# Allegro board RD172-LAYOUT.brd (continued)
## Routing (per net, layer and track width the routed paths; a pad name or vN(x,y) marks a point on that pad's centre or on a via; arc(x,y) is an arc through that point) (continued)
N18175855: length 2.4
  TOP w0.8: D21.A 209.08,140.28 208.3,139.5 R77.2
N18175865: length 4.1
  TOP w1: D21.C 209.8,135.6 208.3,134.1 207.35,134.1
  TOP w1.4: D29.A 207.35,134.1
N18186220: length 22.9
  TOP w0.2: v1(195.2,16.5) 195.89,16.3 206.3,16.3 207.4,17.4 R139.1
  TOP w0.35: 194.21,11.6 v1(195.2,11.6) ; IC19.13 194.32,17.38 v1(195.2,16.5)
  TOP w0.8: R137.1 194.21,11.6
  BOTTOM w0.35: v1(195.2,11.6) 196,12.4 196,15.7 v1(195.2,16.5)
N18186262: length 25.3
  TOP w0.2: R140.1 212.1,16.4 211.5,15.8 194.68,15.8 v1(194.28,16.2)
  TOP w0.35: 194.21,13.2 v1(195.2,13.2) ; IC19.12 193.75,16.73 v1(194.28,16.2)
  TOP w0.8: R138.1 194.21,13.2
  BOTTOM w0.35: v1(194.28,16.2) 195.2,15.28 v1(195.2,13.2)
N18188625: length 135.2
  TOP w1: F1.1 15.25,106 ; F1.1 13.25,108 ; F1.1 13.25,104
  TOP w2: 21,89.6 TB1.2 ; TB1.2 17,87.5 ; TB1.2 13,89.6 ; TB1.2 17,92.35 ; TB1.1 21,98.4 ; TB1.1 17,101.15 ; TB1.1 13,98.4 ; TB1.1 17,95.65
  CONDUCTIVE2 w1: F1.1 15.15,106 ; F1.1 13.25,104.1 ; F1.1 13.25,107.9
  CONDUCTIVE2 w2: 17,87.5 TB1.2 ; TB1.2 TB1.1 ; TB1.2 13,89.6 ; TB1.2 21,89.6 ; TB1.1 13,98.4 ; TB1.1 21,98.4 ; TB1.1 17,102.1
  CONDUCTIVE3 w1: F1.1 13.25,104.1 ; F1.1 13.25,107.9 ; F1.1 15.15,106
  CONDUCTIVE3 w2: TB1.2 17,87.5 ; TB1.2 13,89.6 ; TB1.2 17,92.35 ; TB1.2 21,89.6 ; TB1.1 17,101.5 ; TB1.1 21,98.4 ; TB1.1 13,98.4 ; TB1.1 17,95.5
  BOTTOM w1: F1.1 13.25,104 ; F1.1 15.25,106 ; F1.1 13.25,108
  BOTTOM w2: 17,87.5 TB1.2 ; TB1.2 17,92 ; TB1.2 13,89.6 ; TB1.2 21,89.6 ; TB1.1 17,94.5 ; TB1.1 17,102 ; TB1.1 13,98.4 ; TB1.1 21,98.4
N18188823: length 54.9
  CONDUCTIVE3 w1: C8.1 49,87.3 ; C8.1 47.5,89 ; C8.1 50.7,89 ; C8.1 49,90.7
  CONDUCTIVE3 w1.5: L1.3 64,126.75 ; L1.3 61.75,124.5 ; L1.3 64,122.25 ; L1.3 L2.1 ; L2.1 70,126.75 ; L2.1 70,122.25 ; L2.1 72.25,124.5
  BOTTOM w1: C8.1 49,90.8 ; C8.1 50.8,89 ; C8.1 49,87.2 ; C8.1 47.5,89
  BOTTOM w1.5: L1.3 61.35,124.5 ; L1.3 64,121.85 ; L1.3 L2.1 ; L1.3 64,127.15 ; L2.1 70,121.85 ; L2.1 70,127.15 ; L2.1 72.65,124.5
N18188901: length 24.7
  TOP w1: C9.1 56,87.5 ; C9.1 54.5,89 ; C9.1 57.5,89 ; C9.1 56,90.8
  TOP w3.5: L1.1 L2.3
  CONDUCTIVE2 w1: C9.1 56,87.5 ; C9.1 54.5,89 ; C9.1 57.7,89 ; C9.1 56,90.7
  CONDUCTIVE2 w3.5: L2.3 L1.1
N18189364: length 1.9
  TOP w0.3: 69.6,12.51 69.6,10.99
  TOP w0.8: 69.6,10.99 LED1.A ; R11.2 69.6,12.51
N18189573: length 2.4
  TOP w0.5: 129.15,158.23 128.51,158.23 127.74,159 R13.1
  TOP w0.8: PC2.6 129.15,158.23
N18189577: length 7.6
  TOP w0.3: 137.69,158.7 138.81,158.7 ; 137.31,158.7 136.41,158.7 136.23,158.52 135.85,158.23 ; 139.19,158.7 140.63,158.7 140.83,158.5 142.73,158.5
  TOP w0.8: 137.69,158.7 R15.1 137.31,158.7 ; 139.19,158.7 R14.2 138.81,158.7 ; PC2.1 135.85,158.23
  TOP w1.7: 142.73,158.5 TP12.1
N18189655: length 37.5
  TOP w0.3: v1(128.2,160.77) 128.98,160.77 ; 95.7,161.31 v1(95.7,160.2)
  TOP w0.5: Q2.G R17.2
  TOP w0.8: R17.2 95.7,161.31 ; 128.98,160.77 PC2.4
  BOTTOM w0.3: v1(128.2,160.77) 126.93,159.5 115.4,159.5 114.7,160.2 v1(95.7,160.2)
N18196094: length 1.7
  TOP w0.3: 155.19,55.3 156.52,55.3
  TOP w0.8: 156.52,55.3 R43.1 ; R44.1 155.19,55.3
N18196224: length 1.5
  TOP w0.3: 153.69,53.7 154.81,53.7
  TOP w0.8: 154.81,53.7 R44.2 ; R45.2 153.69,53.7
N18196230: length 1.6
  TOP w0.3: 229.69,51.4 230.91,51.4
  TOP w0.8: 230.91,51.4 R24.2 ; R25.2 229.69,51.4
N18197780: length 1.5
  TOP w0.8: R59.2 R58.2
N18197809: length 1.5
  TOP w0.3: 156.3,143.51 156.3,142.39
  TOP w0.8: R58.1 156.3,143.51 ; 156.3,142.39 R57.1
N18259366: length 2
  TOP w0.35: LED4.C R137.2
N18259444: length 2
  TOP w0.35: LED5.C R138.2
N18316829: length 8.5
  TOP w0.25: 97.7,52.22 97.7,52.67 ; 99.2,51.83 99.2,50.7 R79.1
  TOP w0.3: R78.2 98.4,52.8 97.7,52.8 ; 97.7,52.8 95.6,52.8 95.1,52.3 IC13.13 ; 97.7,52.8 97.7,52.67
  TOP w0.45: C70.1 97.7,52.22
  TOP w0.8: R78.2 99.2,51.83
N18316863: length 14
  TOP w0.3: 95.84,58.1 95.84,57.42 ; 95.84,58.1 95.5,58.1 95.1,57.7 IC13.2 ; 95.84,58.1 99.65,58.1 101.6,56.15 101.6,52.8 R78.1
  TOP w0.5: IC13.1 95.84,57.42
N18316907: length 9.1
  TOP w0.3: 91.76,56.38 91.76,55.7 92.1,55.36 92.5,55.36 ; 92.5,55.36 96.36,55.36 96.8,55.8 97.61,55.8 ; 92.5,55.36 IC13.6
  TOP w0.5: IC13.7 91.76,56.38
  TOP w0.8: 97.61,55.8 R80.1
N18316911: length 8.7
  TOP w0.25: R81.1 100.15,54.12 100.75,54.12 ; 94.45,51.62 94.45,52.9 95.75,54.2 97.63,54.2 ; 97.97,54.2 99.23,54.2
  TOP w0.35: 94.45,51.62 IC13.12
  TOP w0.45: C73.1 100.75,54.12
  TOP w0.8: 99.23,54.2 R81.1 ; 97.63,54.2 R80.2 97.97,54.2
N18317049: length 10.9
  TOP w0.3: TP44.1 93,63.6 94.45,65.05 94.45,66.88 ; IC13.5 93.15,57.9 93,58.05 93,61.93
  TOP w1.5: 94.45,66.88 CT1.VO
  TOP w1.7: 93,61.93 TP44.1
N18317051: length 11.1
  TOP w0.3: IC13.3 94.45,58.1 96.4,60.05 96.4,62.15 ; 96.4,62.47 96.4,65.01 96.36,65.05 96.36,66.88
  TOP w1.5: CT1.VREF 96.36,66.88
  TOP w1.7: 96.4,62.47 TP45.1 96.4,62.15
N18317079: length 7.8
  TOP w0.3: 93.71,48.4 92.49,48.4 ; C74.1 92.3,48.9 93.15,49.75 IC13.10 ; D22.C/A 96,47.35 94.95,48.4 94.09,48.4
  TOP w0.8: 93.71,48.4 R83.1 94.09,48.4 ; 92.49,48.4 C74.1
N18317089: length 11
  TOP w0.2: 93.7,44.2 94.4,44.2 ; 93.7,45.3 94.4,45.3
  TOP w0.3: 97.08,42.5 96,42.5 95.5,43 94.4,43 ; 94.1,41.75 94.1,42.7 94.4,43 ; 94.4,43 94.4,45.8 93.9,46.3 93.9,46.78
  TOP w0.45: 93.58,45.3 93.7,45.3 ; 93.58,44.2 93.7,44.2
  TOP w0.8: 97.08,42.5 R82.1 ; R83.2 93.9,46.78
  TOP w1: 94.1,41.75 CN7.1
N18318229: length 8
  TOP w0.25: v1(265.7,29) 264.77,29
  TOP w0.3: IC16.7 267.4,32.28 v1(267.4,29)
  TOP w0.8: 264.77,29 R112.1
  BOTTOM w0.25: v1(265.7,29) v1(267.4,29)
N18318249: length 6.5
  TOP w0.3: IC16.6 266.5,32.4 266.5,28 R107.1
N18318251: length 8
  TOP w0.3: 264.11,27.4 263.3,27.4 263.1,27.6 262.2,27.6 261.8,27.2 IC17.2 ; 264.3,27.21 264.3,25.79 ; R108.1 265,26.3 265.9,26.3 266,26.2 266,25.74
  TOP w0.45: 266,25.74 C94.1
  TOP w0.8: 264.3,27.21 R107.2 264.11,27.4 ; 264.3,25.79 R108.1
N18318261: length 2.3
  TOP w0.3: IC16.5 263.6,32.5 263.6,32 263.8,31.8 L9.2
N18318275: length 6.4
  TOP w0.3: 263,29.19 263,30.4 263.2,30.6 263.83,30.6 ; 261.5,28.42 261.5,27.8 261.15,27.45 IC17.3 ; 261.69,28.61 262.61,28.61 R112.2
  TOP w0.45: C95.2 263.83,30.6
  TOP w0.8: 261.69,28.61 R113.2 261.5,28.42 ; 263,29.19 R112.2
N18318401: length 5.4
  TOP w0.25: 262.2,18.33 262.2,17.17 ; 262.2,18.62 262.2,19.1 261.8,19.5 261.8,20.07 ; 262.2,16.83 262.2,15.57
  TOP w0.35: IC17.13 261.8,20.07
  TOP w0.8: 262.2,15.57 R95.2 ; 262.2,16.83 R96.1 262.2,17.17 ; 262.2,18.62 C88.1 262.2,18.33
N18318429: length 7.7
  TOP w0.3: 256.69,30 257.81,30 ; IC17.5 259.85,27.55 258,29.4 R126.2 ; 256.5,30.14 256.5,30.62 255.9,31.23 C100.2
  TOP w0.8: 256.5,30.14 R116.2 256.69,30 ; 257.81,30 R126.2
N18318435: length 7.6
  TOP w0.3: 256.69,28.4 258,28.4 259.2,27.2 IC17.6 ; 256.53,26.7 255.4,26.7 C97.1 ; R124.1 256.7,27.5 256.6,27.6 R123.2
  TOP w0.8: R123.2 256.69,28.4 ; R124.1 256.53,26.7
N18318510: length 5.2
  TOP w0.3: IC18.7 253.4,32.78 253.4,30.52 253.92,30 254.71,30
  TOP w0.8: 254.71,30 R116.1
N18318530: length 7
  TOP w0.3: 254.71,28.4 254.1,28.4 252.7,29.8 252.7,32.6 IC18.6
  TOP w0.8: 254.71,28.4 R123.1
N18318540: length 1.6
  TOP w0.3: IC18.5 248.1,33.6 L10.2
N18485742: length 12.2
  TOP w0.4: L4.2 94.72,17.8
  TOP w0.5: L4.2 96.25,16.6 v2(96.3,16.65)
  CONDUCTIVE3 w1: PS9.+VIN 102,17.85 ; PS9.+VIN 100.3,16.65 ; PS9.+VIN 103.3,16.65 ; PS9.+VIN 102,15.4
  BOTTOM w1: 100.2,16.65 PS9.+VIN 104.2,16.65
  vias: v2(94.97,19.63) v2(96.28,18.4)
N18577271: length 8
  TOP w0.25: 117.45,51.33 118.88,51.33 119.2,51 119.2,50.37 ; 117.6,54.63 117.6,53.37 ; 117.6,56.23 117.6,54.97 ; 117.3,51.7 117.3,52.3 117.6,52.6 R94.2
  TOP w0.45: R87.1 119.2,50.37
  TOP w0.6: 117.45,51.33 L5.1 117.3,51.7
  TOP w0.8: 117.6,54.63 C87.1 117.6,54.97 ; R93.2 117.6,56.23 ; 117.6,53.37 R94.2
N18577275: length 18.9
  TOP w0.25: 117.3,47.9 117.3,45.77 118.27,44.8 IC15.2 ; 119.2,48.27 118.8,48.27 ; 119.2,48.27 119.6,48.27 ; 119.2,48.27 119.2,48.67 ; 118.8,48.27 119.2,48.67 ; 118.8,48.27 117.45,48.27 ; 119.6,48.27 121.6,48.27 122.4,49.08 122.4,50.35 ; 119.6,48.27 119.2,48.67 ; 119.2,48.67 119.2,49.18
  TOP w0.3: 122.67,50.6 123.8,50.6 124.2,50.2 124.2,47.94
  TOP w0.45: R87.2 119.2,49.18
  TOP w0.6: 117.45,48.27 L5.4 117.3,47.9
  TOP w0.8: D23.A 124.2,47.94
  TOP w1.7: 122.67,50.6 TP57.1 122.4,50.35
N18577437: length 160.7
  TOP w0.2: 118.27,34.44 118.27,27.63 119.38,26.52 129.47,26.52 134.25,21.75 152.55,21.75 157.33,26.53 223.88,26.53 229.29,21.12 253.01,21.12 254.72,19.41 254.72,15.18 255.51,14.4 259.2,14.4 R98.1
  TOP w1.5: 118.27,34.44 IC15.7
N18577464: length 8.1
  TOP w0.25: 114.4,49.18 114.4,48.67 114.8,48.27 116.15,48.27 ; 116.3,47.9 116.3,46.5 R97.1 115.73,44.8 IC15.3
  TOP w0.45: 114.4,49.18 R100.2
  TOP w0.6: 116.15,48.27 L5.3 116.3,47.9
N18577468: length 164.6
  TOP w0.2: 262.18,13.8 261.2,13.8 261.1,13.9 255.37,13.9 254.28,15 254.28,19.23 252.82,20.68 229.03,20.68 223.71,26 157.6,26 152.85,21.25 134.04,21.25 129.17,26.12 119.08,26.12 115.73,29.47 115.73,34.44
  TOP w0.8: R95.1 262.18,13.8
  TOP w1.5: 115.73,34.44 IC15.6
N18578861: length 8.5
  TOP w0.2: 259.82,16.6 260.8,16.6 261.3,17.1 261.3,18.55 261.15,18.7 261.15,20.07
  TOP w0.3: 259.61,16.6 258.39,16.6 ; 256.79,16.6 258.01,16.6
  TOP w0.35: 261.15,20.07 IC17.12
  TOP w0.8: 258.01,16.6 R99.2 258.39,16.6 ; 259.61,16.6 R98.2 259.82,16.6 ; C89.2 256.79,16.6
N18580990: length 7.8
  TOP w0.5: 237.83,26 238.85,26 240.3,27.45 243,27.45 244,26.45 IC14.1
  TOP w1.7: 237.83,26 TP52.1
N18591595: length 2
  TOP w0.35: 267.21,55.2 267.96,55.2 268.34,54.82 R104.1
  TOP w0.8: 267.21,55.2 R103.2
N18591939: length 1.6
  TOP w0.35: 264.11,58.3 265.29,58.3
  TOP w0.8: 265.29,58.3 R109.1 ; R102.2 264.11,58.3
N18591941: length 1.5
  TOP w0.35: R103.1 266.53,56.7 265.71,56.7
  TOP w0.8: R109.2 265.71,56.7
N18592249: length 1.6
  TOP w0.25: 108,62.63 108,61.37
  TOP w0.8: R88.2 108,62.63 ; 108,61.37 R89.1
N18592251: length 1.6
  TOP w0.25: 108,59.43 108,58.17
  TOP w0.8: R89.2 108,59.43 ; 108,58.17 R90.1
N18592253: length 1.6
  TOP w0.25: 108.17,56.4 109.43,56.4
  TOP w0.8: 109.43,56.4 R91.1 ; R90.2 108.17,56.4
N18592255: length 1.6
  TOP w0.25: 111.37,56.4 112.63,56.4
  TOP w0.8: 112.63,56.4 R92.1 ; R91.2 111.37,56.4
N18592257: length 1.6
  TOP w0.25: 114.57,56.4 115.83,56.4
  TOP w0.8: 115.83,56.4 R93.1 ; R92.2 114.57,56.4
N18593903: length 2.3
  TOP w0.35: R105.1 271.78,53.72 271,54.5 270.51,54.5
  TOP w0.8: 270.51,54.5 R104.2
N18593990: length 2
  TOP w0.35: 271.3,50.21 272,50.91 272,51.49
  TOP w0.8: R106.1 271.3,50.21 ; 272,51.49 R105.2
N18876199: length 9.5
  TOP w2: R4.1 R1.2
N18876231: length 9.5
  TOP w2: R5.1 R2.2
N18995776: length 1.5
  TOP w0.3: L8.2 112.2,34.6 IC15.5
N181610561: length 2.2
  TOP w0.5: 219.6,57.44 219.6,55.77
  TOP w0.8: 219.6,55.77 R23.2
  TOP w1.4: D5.C 219.6,57.44
N181616991: length 2.5
  TOP w0.8: R32.2 203,59.5 D9.C
N181630051: length 2.5
  TOP w0.5: D15.C 173,56.5 173.4,56.1 173.4,55.38
  TOP w0.8: 173.4,55.38 R51.2

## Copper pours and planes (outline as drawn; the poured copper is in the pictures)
5V on TOP (solid shape): 283.49,32.39 283.63,32.04 283.63,32.01 284.14,31.63 283.86,31.05 282.93,30.66 282.46,30.7 282.24,31.12 282.25,31.22 282.28,31.31 282.67,32.24 282.86,32.46 283.13,32.54
5V on CONDUCTIVE3: outline of 148 points within 128.5,1.5 333.5,163.5 ; 143 cut-outs
5V on CONDUCTIVE3: outline of 90 points within 87.6,22.9 136.8,68.3 ; 34 cut-outs
24V on TOP: outline of 100 points within 70.7,11.6 93.9,24 ; 1 cut-out
24V on CONDUCTIVE3: outline of 149 points within 3,3.1 242.8,162.3 ; 41 cut-outs
+5V_AC on CONDUCTIVE3: 107.35,46.75 107.24,46.92 107.2,47.11 107.2,49.3 107.35,49.65 107.7,49.8 119.7,49.8 120.05,49.95 120.2,50.3 120.2,52.99 120.24,53.18 120.35,53.35 123.05,56.05 123.22,56.16 123.41,56.2 135.2,56.2 135.55,56.05 135.7,55.7 135.7,42.1 135.55,41.75 135.2,41.6 112.71,41.6 112.52,41.64 112.35,41.75 ; 6 cut-outs
+14V_M on CONDUCTIVE3: outline of 90 points within 136.5,125.1 216.4,152 ; 33 cut-outs
+14V_N on CONDUCTIVE3: outline of 86 points within 140.1,41.6 191.4,68.3 ; 30 cut-outs
GND on TOP (solid shape): 283.75,35.06 284.33,34.78 284.72,33.85 284.62,33.3 284.07,33.2 283.14,33.59 282.86,34.17 283.37,34.55
GND on TOP: outline of 90 points within 171.9,155.14 219.6,163.3 ; 1 cut-out
GND on TOP: 284,29.1 284.15,29.45 284.5,29.6 290,29.6 290.35,29.75 290.5,30.1 290.5,35.1 290.65,35.45 291,35.6 297.43,35.6 297.62,35.64 297.78,35.75 301.39,39.35 301.55,39.46 301.74,39.5 304.1,39.5 304.45,39.35 304.6,39 304.6,37.53 304.56,37.34 304.45,37.18 296.94,29.67 296.84,29.64 296.77,29.71 296.49,30.14 296,30.3 294,30.3 293.29,29.88 293.34,29.05 293.38,28.95 293.4,28.84 293.4,28.46 293.36,28.26 293.25,28.1 290.3,25.15 290.14,25.04 289.94,25 286.4,25 285.76,25.26 285.5,25.9 285.38,26.32 285.02,26.65 285,26.71 285,27.75 284.85,28.1 284.5,28.25 284.2,28.25 284.16,28.25 284.11,28.24 284.03,28.27 284,28.34 ; 1 cut-out
GND on TOP: outline of 523 points within 118.87,14.8 276,38.5 ; 1 cut-out
GND on TOP: 134.5,163.5 134.65,163.85 135,164 174,164 174.35,163.85 174.5,163.5 174.5,161.56 174.46,161.36 174.35,161.2 172.4,159.25 172.24,159.14 172.04,159.1 151.69,159.1 151.62,159.12 151.32,159.66 150.8,159.85 149,159.85 148.58,159.73 148.29,159.42 148.28,159.4 148.26,159.38 148.19,159.36 148.13,159.39 146.77,160.75 146.61,160.86 146.42,160.9 140,160.9 139.85,160.93 139.71,161 139.45,161.15 139.15,161.2 137.4,161.2 137.14,161.16 136.91,161.03 136.81,161.02 136.75,161.11 136.56,161.51 136.15,161.67 135.15,161.67 134.89,161.61 134.68,161.44 134.67,161.43 134.56,161.41 134.5,161.5 ; 1 cut-out
GND on TOP: 217.59,18.4 217.55,18.41 217.52,18.43 216.02,19.92 215.83,20.05 215.6,20.1 207,20.1 206.77,20.05 206.58,19.92 206.1,19.45 205.94,19.34 205.74,19.3 197.3,19.3 197.23,19.33 197.2,19.4 197.2,20.03 197.21,20.07 197.35,20.33 197.4,20.6 197.4,21.2 197.43,21.27 197.5,21.3 197.9,21.3 198.1,21.33 198.33,21.4 199.61,21.4 199.68,21.38 199.98,20.84 200.5,20.65 202.3,20.65 202.67,20.74 202.96,21 203,21.07 203.04,21.14 203.07,21.18 203.13,21.2 203.8,21.2 204.18,21.29 204.46,21.55 204.52,21.59 204.6,21.58 204.74,21.52 204.9,21.5 206.63,21.5 206.66,21.5 206.68,21.48 206.75,21.44 207.2,21.3 207.65,21.44 207.72,21.48 207.74,21.5 207.77,21.5 222.2,21.5 222.23,21.49 222.27,21.47 224.77,18.97 224.79,18.93 224.8,18.9 224.8,18.5 224.77,18.43 224.7,18.4
GND on TOP: outline of 612 points within 87.6,1 334,153.13 ; 6 cut-outs
GND on BOTTOM: outline of 91 points within 133.7,155.15 322.71,164 ; 3 cut-outs
GND on BOTTOM: 88.99,51.49 89.5,53 89.5,65.1 89.65,65.45 90,65.6 99.16,65.6 99.35,65.56 99.51,65.45 102.06,62.91 102.16,62.75 102.2,62.56 102.2,44.97 102.24,44.78 102.35,44.62 110.22,36.75 110.38,36.64 110.57,36.6 126.6,36.6 126.95,36.45 127.1,36.1 127.1,32.85 128.5,31.48 129.9,32.85 129.9,36.1 130.05,36.45 130.4,36.6 136.4,36.6 136.75,36.45 136.9,36.1 136.9,32.16 136.86,31.97 136.75,31.81 135.05,30.1 134.94,29.94 134.9,29.75 134.9,24.3 134.89,24.26 134.87,24.23 133.57,22.93 133.54,22.91 133.5,22.9 128.6,22.9 128.53,22.93 128.5,23 128.5,23.5 128.21,24.21 127.5,24.5 124.5,24.5 123.79,24.21 123.5,23.5 123.5,23 123.47,22.93 123.4,22.9 103.8,22.9 103.45,23.05 103.3,23.4 103.3,31.9 102,33.19 100.7,31.9 100.7,23.4 100.55,23.05 100.2,22.9 94.86,22.9 94.67,22.94 94.51,23.04 87.74,29.81 87.64,29.97 87.6,30.16 87.6,50.5 87.62,50.56 ; 5 cut-outs
GND on BOTTOM: outline of 121 points within 132.5,1 334,151.5 ; 27 cut-outs
GND on CONDUCTIVE2: outline of 200 points within 87.6,1.5 333.5,163.4 ; 91 cut-outs
GND_5VDC on BOTTOM: 261.9,41.5 260.9,42.5 259.9,41.5 259.9,40.8 259.87,40.73 259.8,40.7 247.3,40.7 247.26,40.71 247.22,40.73 246.37,41.37 245.33,41.6 245.1,41.7 245,41.93 245,46 245.15,46.35 245.5,46.5 256.5,46.5 256.5,47.46 256.51,47.5 256.53,47.53 257.97,48.97 258,48.99 258.04,49 261.96,49 262,48.99 262.03,48.97 264.4,46.6 270.9,46.6 270.9,48.16 270.91,48.2 270.93,48.23 271.67,48.97 271.7,48.99 271.74,49 280.59,49 280.84,49.07 280.95,49.15 281.12,49.26 281.31,49.3 291.4,49.3 292.11,49.01 292.4,48.3 292.4,41.7 292.11,40.99 291.4,40.7 284.34,40.7 284.31,40.71 284.25,40.78 284.27,40.87 284.29,40.88 283.5,43.44 282.71,40.88 282.73,40.87 282.75,40.78 282.69,40.71 282.66,40.7 262,40.7 261.93,40.73 261.9,40.8 ; 2 cut-outs
GND_5VDC on CONDUCTIVE2: 280.59,49 280.78,49.04 280.95,49.15 280.95,49.15 281.12,49.26 281.31,49.3 291.9,49.3 292.25,49.15 292.4,48.8 292.4,41.2 292.25,40.85 291.9,40.7 285.4,40.7 285.05,40.85 284.9,41.2 284.9,42 283.5,43.44 282.1,42 282.1,41.2 281.95,40.85 281.6,40.7 260.91,40.7 260.89,40.7 247.3,40.7 247.26,40.71 247.22,40.73 246.37,41.37 245.33,41.6 245.1,41.7 245,41.93 245,46 245.15,46.35 245.5,46.5 256,46.5 256.35,46.65 256.5,47 256.5,47.29 256.54,47.48 256.65,47.65 257.85,48.85 258.02,48.96 258.21,49 261.79,49 261.98,48.96 262.15,48.85 264.25,46.75 264.42,46.64 264.61,46.6 270.4,46.6 270.75,46.75 270.9,47.1 270.9,47.99 270.94,48.18 271.05,48.35 271.55,48.85 271.72,48.96 271.91,49 ; 3 cut-outs
GND_24V on TOP: outline of 281 points within 3.1,3.1 120,162.4 ; 4 cut-outs
GND_24V on BOTTOM: outline of 168 points within 3.1,3.1 242.87,162.4 ; 14 cut-outs
GND_24V on CONDUCTIVE2: 7,20.67 7.04,20.48 7.15,20.32 19.82,7.65 19.98,7.54 20.17,7.5 48,7.5 49.43,7.95 50.35,9.13 50.46,9.56 50.5,10 50.5,27.55 50.58,27.93 50.79,28.26 72.89,50.36 73.05,50.46 73.24,50.5 84.9,50.5 85.25,50.35 85.4,50 85.4,29.25 85.44,29.06 85.55,28.9 93.6,20.85 93.76,20.74 93.95,20.7 111.9,20.7 112.25,20.55 112.4,20.2 112.4,3.71 112.36,3.52 112.25,3.35 112.15,3.25 111.98,3.14 111.79,3.1 19.16,3.1 18.97,3.14 18.81,3.25 2.85,19.21 2.74,19.37 2.7,19.56 2.7,145.64 2.74,145.83 2.85,145.99 9.93,153.07 11.01,153.99 11.93,155.07 19.01,162.15 19.17,162.26 19.36,162.3 131,162.3 131.35,162.15 131.5,161.8 131.5,147 131.35,146.65 131,146.5 125.5,146.5 125.15,146.65 125,147 125,151 124.85,151.35 124.5,151.5 82,151.5 81.65,151.65 81.5,152 81.5,155 81.35,155.35 81,155.5 18.17,155.5 17.98,155.46 17.82,155.35 7.15,144.68 7.04,144.52 7,144.33 ; 22 cut-outs
GND_M on TOP: 151.64,149 151.61,149.01 151.57,149.03 151.1,149.5 150.83,149.69 150.5,149.75 149.75,149.75 149.71,149.76 149.37,149.88 149.36,149.89 149.16,149.97 148.95,150 145.84,150 145.81,150.01 145.77,150.03 145.6,150.2 145.33,150.39 145,150.45 143.92,150.45 143.89,150.45 143.87,150.46 142.3,150.83 141.54,150.15 141.45,150.09 140.18,150.9 138.91,150.09 138.82,150.15 137.83,150.89 136.67,150.47 136.56,150.44 136.5,150.54 136.5,151.9 136.53,151.97 136.6,152 152.9,152 152.97,151.97 153,151.9 153,151.68 152.99,151.63 152.69,151.31 152.6,150.93 152.6,149.1 152.57,149.03 152.5,149
GND_M on TOP: 182.51,136.16 182.3,136.42 182.27,136.5 182.3,136.58 182.52,136.86 182.6,137.2 182.6,137.4 182.55,137.67 182.41,137.93 182.4,137.97 182.4,139.27 182.4,139.3 182.42,139.32 182.51,139.55 182.51,139.79 182.5,139.95 182.55,140.11 182.59,140.23 182.6,140.36 182.6,140.41 182.63,140.5 182.72,140.52 182.81,140.51 182.9,140.5 183.1,140.5 183.28,140.52 183.46,140.58 183.55,140.58 183.6,140.49 183.6,138.5 183.73,138.06 184.09,137.76 184.15,137.71 184.15,137.63 184.11,137.52 184.1,137.4 184.1,136.88 184.08,136.82 184.03,136.78 183.32,136.4 182.78,135.79 182.67,135.75 182.6,135.84
GND_M on TOP: 202.46,145.06 202.43,145.13 202.46,145.2 203.55,146.28 203.59,146.31 203.64,146.31 203.74,146.29 203.84,146.28 203.89,146.28 203.97,146.29 204.05,146.3 204.13,146.28 204.17,146.2 204.17,145.42 204.12,145.34 204.03,145.33 203.87,145.38 203.7,145.4 203.5,145.4 203.07,145.27 202.77,144.94 202.7,144.88 202.61,144.91
GND_M on TOP: outline of 135 points within 190.41,119.6 219.4,150
GND_M on BOTTOM: outline of 101 points within 136.5,132 190.91,152 ; 3 cut-outs
GND_M on BOTTOM: 199.3,138.6 199.15,138.95 198.8,139.1 196.7,139.1 196.35,138.95 196.2,138.6 196.2,138.2 196,138 195.8,138.2 195.8,138.3 195.57,138.86 195.01,139.1 194.91,139.2 195.01,139.3 195.85,139.3 196.2,139.45 196.35,139.8 196.35,142.2 196.2,142.55 195.85,142.7 194.15,142.7 193.8,142.55 193.65,142.2 193.65,140.1 193.88,139.54 194.44,139.3 194.54,139.2 194.44,139.1 192,139.1 191.65,139.25 191.5,139.6 191.5,149.5 191.65,149.85 192,150 211.94,150 212.01,149.98 212.04,149.91 213.5,147.15 216.4,146 216.47,145.97 216.5,145.9 216.5,139 216.44,138.76 216.26,138.57 216.13,138.52 216,138.5 213.61,138.5 213.36,138.43 213.25,138.35 208.66,133.76 208.61,133.73 208.56,133.74 207.24,133.99 205.9,133.87 205.9,133.87 204.89,133.5 203.99,132.92 203.95,132.9 203.92,132.9 203.4,132.9 203.33,132.93 203.3,133 202.75,134.27 201.46,134.75 201.45,134.75 198.5,134.75 198.15,134.89 198,135.25 198,136 198.15,136.35 198.5,136.5 198.8,136.5 199.15,136.65 199.3,137 ; 1 cut-out
GND_N on TOP: outline of 91 points within 175,43.5 187.2,68.5
GND_N on TOP: outline of 181 points within 142.81,41.6 168.7,57
GND_N on TOP: outline of 97 points within 140.1,41.6 160.5,67
GND_N on BOTTOM: outline of 119 points within 173.3,43.5 187.4,65.26
GND_N on BOTTOM: outline of 115 points within 140,41.6 169.03,67 ; 1 cut-out
GND_N on CONDUCTIVE2: outline of 107 points within 140.1,41.6 191.4,69.5 ; 14 cut-outs
GND_P on TOP: 236.8,41.6 236.45,41.75 236.3,42.1 236.3,43.07 236.3,45.61 236.3,48.09 235.71,49.21 234.46,49.3 233.94,49.07 233.84,49.03 233.73,49.02 233.43,49.02 233.24,48.98 233.08,48.87 232.35,48.15 232.19,48.04 232,48 229.2,48 229.13,48.03 229.1,48.1 229.1,48.8 229.13,48.87 229.2,48.9 229.6,48.9 230.17,49.13 230.4,49.7 230.4,50.4 230.43,50.47 230.5,50.5 231.2,50.5 231.77,50.73 232,51.3 232,51.5 232,51.6 232,53.49 232.05,53.57 232.15,53.58 237.1,51.55 242.4,50.76 242.47,50.73 242.5,50.66 242.5,42.1 242.35,41.75 242,41.6
GND_P on TOP: 212.96,47.12 212.87,47.11 212.86,47.12 212.67,47.19 212.47,47.22 212.42,47.22 212.32,47.21 212.2,47.19 212.13,47.22 212.1,47.29 212.1,47.44 212.13,47.59 212.3,47.84 212.32,47.98 212.32,57.15 212.47,57.5 212.82,57.65 212.9,57.65 214.11,57.99 214.96,58.92 214.97,58.95 214.99,58.96 215.03,58.98 215.07,58.98 215.1,58.97 215.12,58.95 215.38,58.76 215.7,58.7 215.9,58.7 215.97,58.7 216.07,58.72 216.16,58.65 216.14,58.54 215.61,58.02 215.53,57.9 215.47,57.61 215.39,57.49 215,57.1 214.89,56.93 214.85,56.74 214.85,50.69 214.84,50.65 214.82,50.62 214.81,50.61 213.76,49.5 213.14,48.1 213.05,47.65 213,47.2
GND_P on TOP: outline of 191 points within 191.3,43.5 212.7,62.91
GND_P on TOP: 195.75,62.1 195.68,62.13 195.65,62.2 195.34,63.8 194.46,65.17 194.2,65.55 193.92,65.89 193.91,65.9 193.9,65.92 193.84,66.11 193.81,66.22 193.8,66.25 193.8,68 193.95,68.35 194.3,68.5 195.52,68.5 195.59,68.47 195.62,68.4 195.62,67.55 195.8,67.13 196.22,66.95 199.25,66.95 199.32,66.92 199.35,66.85 199.35,65.99 199.31,65.91 199.23,65.89 199.17,65.9 199.1,65.9 198.9,65.9 198.33,65.67 198.1,65.1 198.1,62.5 198.09,62.46 198.07,62.43 198.03,62.38 197.96,62.3 197.89,62.19 197.83,62.13 197.8,62.11 197.76,62.1
GND_P on TOP: outline of 105 points within 219.28,41.6 233.7,65.48
GND_P on BOTTOM: 221.15,41.6 221.08,41.63 221.05,41.7 221.05,44.2 221.06,44.23 221.07,44.26 222,47 221.07,49.74 221.06,49.77 221.05,49.8 221.05,57.1 221.08,57.17 221.15,57.2 222.8,57.2 223.37,57.43 223.6,58 223.6,62.9 223.63,62.97 223.7,63 224.06,63 224.1,62.99 224.13,62.97 227.92,59.18 227.94,59.15 227.95,59.11 227.95,58.05 227.94,58.01 227.92,57.98 227.68,57.73 227.65,57.71 227.61,57.7 227.47,57.69 227.33,57.66 227.31,57.66 227.29,57.66 227.2,57.68 226,56.66 227.27,55.74 227.3,55.74 227.33,55.74 227.66,55.7 227.98,55.77 228.04,55.78 228.1,55.74 228.38,55.49 228.75,55.4 231.66,55.4 231.7,55.39 231.73,55.37 234.65,52.45 234.82,52.34 235.01,52.3 242,52.3 242.35,52.15 242.5,51.8 242.5,42.1 242.35,41.75 242,41.6 236.8,41.6 236.45,41.75 236.3,42.1 236.3,48.1 235,49.42 233.7,48.1 233.7,42.1 233.55,41.75 233.2,41.6
GND_P on BOTTOM: outline of 139 points within 191.4,43.5 216.8,65 ; 1 cut-out
GND_P on BOTTOM: 194.72,62.1 194.67,62.11 194.64,62.15 194.44,62.42 194.23,62.68 194.21,62.71 194.2,62.75 194.2,64.4 194.04,65.79 193.51,67.1 193.5,67.12 193.5,67.15 193.5,70.04 193.54,70.23 193.65,70.4 196,72.75 196.17,72.86 196.36,72.9 207.45,72.9 207.5,72.89 207.54,72.85 207.66,72.63 207.79,72.43 207.8,72.38 207.79,72.33 207.27,70.4 207.5,68.41 207.5,68.38 207.5,66.35 207.47,66.28 207.4,66.25 207,66.25 205.79,65.72 205.3,64.5 205.3,64.1 205.27,64.03 205.2,64 199.1,64 197.23,62.13 197.2,62.11 197.16,62.1
GND_P on CONDUCTIVE2: outline of 103 points within 191.4,41.6 242.5,72.9 ; 14 cut-outs
AC_L on BOTTOM: outline of 90 points within 109.3,110.35 165,146.5 ; 5 cut-outs
AC_L_IN on BOTTOM: outline of 125 points within 12,12.5 150.1,146.5 ; 15 cut-outs
AC_L_IN on CONDUCTIVE2: outline of 196 points within 12,12.5 153.55,146.5 ; 16 cut-outs
AC_N on BOTTOM: 134.3,72.6 134.27,72.53 134.2,72.5 107.02,72.5 106.94,72.54 106.32,75.24 103.9,76.4 101.85,76.4 101.5,76.55 101.35,76.9 101.35,79.82 99.9,81.33 98.35,79.91 98.35,79.78 98.35,77.34 98.35,77.24 98.35,74.8 98.35,74.8 99.07,73.47 100.58,73.44 100.6,73.45 100.63,73.45 100.7,73.42 100.73,73.35 100.7,72.98 100.73,72.6 100.7,72.53 100.63,72.5 99.58,72.5 99.54,72.51 99.51,72.53 99.47,72.57 98.66,73.11 97.7,73.3 95.3,73.3 94.73,73.53 94.5,74.1 94.5,85.17 94.56,85.47 94.73,85.73 98.27,89.27 98.53,89.44 98.83,89.5 134.2,89.5 134.27,89.47 134.3,89.4 ; 2 cut-outs
AC_N_IN on TOP: outline of 172 points within 12,12.5 164.8,146.1 ; 13 cut-outs
AC_N_IN on CONDUCTIVE3: outline of 130 points within 12,12.5 164.8,146 ; 19 cut-outs
AD1 on TOP: 91.57,50.47 91.52,50.75 91.75,50.9 91.78,50.9 92.01,50.75 91.95,50.47 91.94,50.46 91.76,50.39 91.59,50.46
AD1 on TOP: 91.56,49.6 91.53,49.6 91.42,49.71 91.46,49.86 91.66,50.06 91.76,50.1 91.87,50.06 92.07,49.86 92.1,49.82 92.09,49.67 91.96,49.6
FG on CONDUCTIVE3: 45.49,69.5 45.31,69.47 45.17,69.37 44.65,69.1 44.23,68.77 41.11,65.65 40.95,65.54 40.76,65.5 12.6,65.5 12.25,65.65 12.1,66 12.1,81 12.25,81.35 12.6,81.5 70,81.5 70.35,81.35 70.5,81 70.5,72.41 70.46,72.22 70.35,72.05 67.95,69.65 67.78,69.54 67.59,69.5 ; 9 cut-outs
SIG1 on BOTTOM: 24.8,112.3 24.65,112.65 24.3,112.8 12.5,112.8 12.15,112.95 12,113.3 12,128.55 12.15,128.9 12.5,129.05 18.75,129.05 22,130.41 23.3,133.69 23.3,133.7 23.3,146.45 23.15,146.8 22.8,146.95 17.71,146.95 17.25,147.26 17.35,147.8 19.9,150.35 20.07,150.46 20.26,150.5 53.5,150.5 53.85,150.35 54,150 54,105.21 53.96,105.02 53.85,104.85 44.15,95.15 44.04,94.98 44,94.79 44,87 43.85,86.65 43.5,86.5 40.7,86.5 40.35,86.65 40.2,87 40.2,87.33 40.2,87.35 40.21,87.37 37,92.6 33.79,87.37 33.8,87.35 33.8,87.33 33.8,87 33.65,86.65 33.3,86.5 25.3,86.5 24.95,86.65 24.8,87 ; 10 cut-outs
SIG1 on CONDUCTIVE2: 42.25,124.5 42.3,124.1 42.3,124.07 42.3,118.9 42.29,118.85 42.25,118.81 40.25,115.5 42.25,112.19 42.29,112.15 42.3,112.1 42.3,107.9 42.15,107.55 41.8,107.4 40.8,107.4 39.35,106 40.8,104.6 41.8,104.6 42.15,104.45 42.3,104.1 42.3,103.48 42.45,103.12 42.8,102.98 49.5,102.98 49.85,102.83 50,102.48 50,101.21 49.96,101.02 49.85,100.85 44.15,95.15 44.04,94.98 44,94.79 44,87 43.85,86.65 43.5,86.5 40.7,86.5 40.35,86.65 40.2,87 40.2,89 37,92.2 33.8,89 33.8,87 33.65,86.65 33.3,86.5 25.3,86.5 24.95,86.65 24.8,87 24.8,112.3 24.65,112.65 24.3,112.8 12.5,112.8 12.15,112.95 12,113.3 12,128.55 12.15,128.9 12.5,129.05 18.75,129.05 22,130.41 23.3,133.69 23.3,133.7 23.3,150 23.45,150.35 23.8,150.5 53.5,150.5 53.85,150.35 54,150 54,137.48 53.85,137.12 53.5,136.98 42.8,136.98 42.45,136.83 42.3,136.48 42.3,124.93 42.3,124.9 ; 7 cut-outs
SIG2 on TOP: outline of 94 points within 12,86.5 54,150.5 ; 6 cut-outs
VDC_M on TOP: 185.64,69.4 185.29,69.55 185.15,69.9 185.15,69.9 183.55,71.65 181.85,70 181.85,69.97 181.71,69.64 181.37,69.5 181.34,69.5 181.3,69.53 181.12,70.02 180.9,70.45 180.72,70.73 180.52,70.99 180.51,71.02 180.5,71.06 180.5,80.69 180.54,80.88 180.65,81.05 184.75,85.15 184.92,85.26 185.11,85.3 197.34,85.3 197.53,85.26 197.69,85.15 202.35,80.49 202.46,80.33 202.5,80.14 202.5,70.9 202.35,70.55 202,70.4 201.68,70.4 201.53,70.42 201.4,70.49 201.39,70.49 200.39,70.49 200.32,70.51 200.29,70.59 200.29,72.14 200.32,72.21 200.39,72.24 201.18,72.24 201.18,74.35 201.03,74.7 200.68,74.85 200.03,74.85 199.87,74.83 199.67,74.75 199.62,74.77 199.47,74.83 199.31,74.85 196.12,74.85 195.77,74.7 195.62,74.35 195.62,72.23 196.29,72.23 196.36,72.2 196.39,72.13 196.39,70.58 196.36,70.51 196.29,70.48 195.62,70.48 195.62,70.15 195.47,69.8 195.12,69.65 189,69.65 188.18,69.59 187.35,69.4
VDC_M on BOTTOM: outline of 111 points within 148,69.7 202.4,130.4 ; 4 cut-outs
VDC_M_DCT on TOP: outline of 130 points within 216,101.3 246.3,108.7
VDC_M_DCT on BOTTOM: outline of 91 points within 206.2,69.5 289,136.5 ; 20 cut-outs
VDC_N on TOP: 217,92.5 216.29,92.79 216,93.5 216,97.53 216.28,98.22 216.97,98.5 217,98.49 217.06,98.44 217.07,98.37 217.02,98.21 217,98.05 217,97.55 217.23,96.98 217.8,96.75 222.2,96.75 222.77,96.98 223,97.55 223,98.05 222.98,98.21 222.93,98.4 222.96,98.47 223.03,98.5 223.47,98.5 223.55,98.46 223.57,98.37 223.52,98.21 223.5,98.05 223.5,97.55 223.73,96.98 224.3,96.75 228.7,96.75 229.27,96.98 229.5,97.55 229.5,98.05 229.48,98.21 229.43,98.4 229.46,98.47 229.53,98.5 229.97,98.5 230.04,98.47 230.07,98.4 230.02,98.21 230,98.05 230,97.55 230.23,96.98 230.8,96.75 235.2,96.75 235.77,96.98 236,97.55 236,98.05 235.99,98.16 235.97,98.27 235.98,98.36 236.06,98.4 236.37,98.4 236.45,98.36 236.46,98.26 236.42,98.11 236.4,97.95 236.4,96.6 236.63,96.03 237.2,95.8 239.8,95.8 240.37,96.03 240.6,96.6 240.6,97.95 240.58,98.11 240.54,98.26 240.55,98.36 240.63,98.4 242.9,98.4 242.97,98.37 243,98.3 243,95.35 242.97,95.28 242.9,95.25 237.43,94.54 232.31,92.51 232.28,92.5 232.26,92.5
VDC_N on TOP: 162,65.3 161.65,65.45 161.5,65.8 161.5,94.7 161.65,95.05 162,95.2 166.7,95.2 167.05,95.05 167.2,94.7 167.2,93.48 167.19,93.45 167.18,93.41 167.15,93.39 166.6,93.04 166.1,92.63 165.98,92.61 165.93,92.72 163.28,93.93 165.08,91.63 165.12,91.64 165.2,91.6 165.22,91.52 165.21,91.49 165.21,86.5 169.54,84 173.7,84 174.05,83.85 174.2,83.5 174.2,65.8 174.05,65.45 173.7,65.3 170.78,65.3 170.43,65.45 170.28,65.8 170.28,66.21 169.53,66.21 169.46,66.23 169.43,66.31 169.43,67.86 169.46,67.93 169.53,67.96 170.28,67.96 170.28,69.95 170.21,70.2 170.03,70.38 169.78,70.45 169.13,70.45 168.97,70.43 168.82,70.36 168.79,70.35 168.76,70.35 168.72,70.36 168.57,70.43 168.41,70.45 165.22,70.45 164.87,70.3 164.72,69.95 164.72,67.88 165.45,67.88 165.52,67.85 165.55,67.78 165.55,66.23 165.52,66.16 165.45,66.13 164.72,66.13 164.72,65.8 164.57,65.45 164.22,65.3
VDC_N on BOTTOM: outline of 81 points within 220.5,69.5 318,156.3 ; 4 cut-outs
VDC_N on CONDUCTIVE2: outline of 242 points within 157.55,58.8 318,156.3 ; 26 cut-outs
VDC_P on TOP: outline of 272 points within 166.9,69.5 318,156.3 ; 5 cut-outs
VDC_P on CONDUCTIVE3: outline of 179 points within 166.9,58 318,156.3 ; 26 cut-outs
N18160932 on TOP (solid shape): 217.26,64.36 217.35,64.25 217.41,64.11 218.16,63.87 218.29,63.95 218.63,63.86 218.55,63.52 217.66,62.97 217.45,62.95 217.29,63.09 216.89,64.05 216.88,64.1 216.87,64.15 216.94,64.33 217.12,64.4
N18160932 on TOP: 216.74,56.4 216.7,56.41 216.67,56.43 216.03,57.07 216.01,57.1 216,57.14 216,57.66 216.01,57.7 216.03,57.73 216.97,58.67 217,58.69 217.04,58.7 217.95,58.7 218.02,58.67 218.05,58.6 218.05,56.5 218.02,56.43 217.95,56.4
N18160932 on BOTTOM: outline of 96 points within 204.2,47.3 222,69.5
N18160956 on TOP: 216.24,51.85 216.2,51.86 216.17,51.88 215.38,52.67 215.36,52.7 215.35,52.74 215.35,54 215.38,54.07 215.45,54.1 215.77,54.1 215.85,54.06 215.87,53.98 215.86,53.89 215.85,53.8 215.85,53.6 216.08,53.03 216.65,52.8 217.35,52.8 217.92,53.03 218.15,53.6 218.15,53.8 218.14,53.89 218.13,53.98 218.15,54.06 218.23,54.1 218.37,54.1 218.45,54.06 218.47,53.98 218.46,53.89 218.45,53.8 218.45,53.6 218.68,53.03 219.25,52.8 219.95,52.8 220.45,52.97 220.73,53.42 220.84,53.5 220.93,53.4 220.93,52.42 220.92,52.38 220.9,52.35 220.43,51.88 220.4,51.86 220.36,51.85
N18160956 on BOTTOM: 206.04,47.37 206,47.37 205.97,47.4 205.93,47.44 205.91,47.47 205.9,47.51 205.9,48.29 205.91,48.33 205.93,48.36 206.14,48.57 206.17,48.59 206.21,48.6 207.9,48.6 212.15,52.85 212.32,52.96 212.51,53 219.84,53 220.03,52.96 220.2,52.85 220.4,52.65 220.51,52.48 220.55,52.29 220.55,52 220.4,51.65 220.05,51.5 212.6,51.5 212.41,51.46 212.24,51.35 208.29,47.4 208.25,47.37 208.22,47.37
N18161570 on BOTTOM: 192.9,48.29 192.94,48.48 193.05,48.65 196.35,51.95 196.46,52.12 196.5,52.31 196.5,57.88 196.54,58.07 196.65,58.23 197.4,58.99 197.62,59.31 197.7,59.7 197.7,61.19 197.74,61.38 197.85,61.55 198.75,62.45 198.92,62.56 199.11,62.6 201.32,62.6 201.62,62.47 201.75,62.17 201.75,60.7 201.6,60.35 201.25,60.2 199.45,60.2 199.1,60.05 198.95,59.7 198.95,57.3 199.1,56.95 199.45,56.8 200.4,56.8 200.6,56.6 200.4,56.4 199.41,56.4 199.22,56.36 199.05,56.25 198.7,55.9 198.59,55.73 198.55,55.54 198.55,52.6 198.52,52.53 197.78,52.19 197.5,51.5 197.5,50.7 197.46,50.51 197.35,50.35 195.75,48.74 195.58,48.63 195.39,48.59 194.9,48.59 194.8,48.6 194.6,48.58 194.13,48.34 193.85,47.9 193.81,47.75 193.8,47.59 193.8,47.45 193.35,47 192.9,47.45
N18161621 on TOP: 199.44,54.5 199.4,54.51 199.37,54.53 198.63,55.27 198.61,55.3 198.6,55.34 198.6,57.15 198.63,57.22 198.7,57.25 198.76,57.25 198.84,57.21 198.86,57.13 198.85,57.07 198.85,57 198.85,56.8 199.08,56.23 199.65,56 200.35,56 200.92,56.23 201.15,56.8 201.15,57 201.14,57.09 201.13,57.18 201.15,57.27 201.23,57.31 201.77,57.31 201.85,57.27 201.87,57.18 201.86,57.09 201.85,57 201.85,56.8 202.08,56.23 202.65,56 203.35,56 203.44,56.01 203.53,56.02 203.61,56 203.65,55.92 203.65,55.45 203.64,55.41 203.62,55.38 202.77,54.53 202.74,54.51 202.7,54.5
N18162177 on BOTTOM: outline of 92 points within 178.8,47.1 191.3,66
N18162199 on TOP: 187.64,51.2 187.6,51.21 187.57,51.23 186.63,52.17 186.61,52.2 186.6,52.24 186.6,53.5 186.63,53.57 186.7,53.6 186.76,53.6 186.83,53.57 186.85,53.49 186.85,53.44 186.85,53.4 186.85,53.2 187.08,52.63 187.65,52.4 188.35,52.4 188.92,52.63 189.15,53.2 189.15,53.4 189.15,53.44 189.15,53.49 189.17,53.57 189.24,53.6 189.36,53.6 189.43,53.57 189.45,53.49 189.45,53.44 189.45,53.4 189.45,53.2 189.68,52.63 190.25,52.4 190.95,52.4 191.52,52.63 191.75,53.2 191.75,53.4 191.75,53.44 191.75,53.49 191.77,53.57 191.84,53.6 191.9,53.6 191.97,53.57 192,53.5 192,51.84 191.99,51.8 191.97,51.77 191.43,51.23 191.4,51.21 191.36,51.2
N18162199 on BOTTOM: 180.9,47.1 180.79,47.11 180.69,47.15 180.59,47.18 180.49,47.2 180.43,47.23 180.4,47.3 180.4,47.76 180.41,47.8 180.43,47.83 181.97,49.37 182,49.39 182.04,49.4 182.6,49.4 182.98,49.47 183.3,49.68 183.35,49.74 183.41,49.81 186.47,52.87 186.5,52.89 186.54,52.9 191.16,52.9 191.2,52.89 191.23,52.87 191.77,52.33 191.79,52.3 191.8,52.26 191.8,51.54 191.79,51.5 191.77,51.47 191.43,51.13 191.4,51.11 191.36,51.1 186,51.1 182.03,47.13 182,47.11 181.96,47.1
N18162894 on TOP: 171.21,55.96 170.95,56 170.25,56 170.1,55.98 169.95,55.94 169.89,55.93 169.84,55.96 169.33,56.47 169.31,56.5 169.3,56.54 169.3,58.4 169.33,58.47 169.4,58.5 169.71,58.5 170.27,58.74 170.5,59.3 170.5,61.1 170.48,61.29 170.4,61.49 170.4,61.51 170.32,61.72 170.11,61.8 170.09,61.8 169.89,61.88 169.7,61.9 169.32,61.9 169.09,61.99 169.09,62.46 169.32,62.55 169.78,62.55 170.13,62.7 170.28,63.05 170.28,63.9 170.31,63.97 170.38,64 170.45,64 173.3,64 173.37,63.97 173.4,63.9 173.4,63.1 173.37,63.03 173.3,63 172.25,63 171.68,62.77 171.45,62.2 171.45,61.4 171.48,61.17 171.6,60.93 171.6,60.9 171.6,58.3 171.6,58.27 171.48,58.03 171.45,57.8 171.45,57 171.48,56.77 171.6,56.53 171.6,56.5 171.6,55.91 171.54,55.82 171.44,55.83
N18162894 on BOTTOM: 157.93,47.1 157.85,47.13 157.82,47.2 157.82,48.48 157.83,48.52 157.85,48.55 160.07,50.77 160.1,50.79 160.14,50.8 161.6,50.8 166.49,55.69 166.61,55.79 166.71,55.91 169.57,58.77 169.6,58.79 169.64,58.8 170.95,58.8 171.35,59.2 171.35,62.3 171.38,62.37 171.45,62.4 172.3,62.4 172.37,62.37 172.4,62.3 172.4,56.34 172.39,56.3 172.37,56.27 170.13,54.03 170.1,54.01 170.06,54 167.1,54 165.88,52.78 165.82,52.72 162.52,49.43 162.49,49.41 162.45,49.4 160.58,49.4 160.42,49.38 160.27,49.31 160.23,49.3 159.41,48.48 159.39,48.46 159.07,48.16 158.91,47.76 158.9,47.68 158.9,47.6 158.9,47.2 158.87,47.13 158.8,47.1
N18162939 on TOP: 169.3,51.3 169.23,51.33 169.2,51.4 169.2,53.6 169.23,53.67 169.3,53.7 169.37,53.7 169.45,53.66 169.47,53.58 169.46,53.49 169.45,53.4 169.45,53.2 169.68,52.63 170.25,52.4 170.95,52.4 171.52,52.63 171.75,53.2 171.75,53.4 171.74,53.49 171.73,53.58 171.75,53.66 171.83,53.7 172.17,53.7 172.25,53.66 172.27,53.58 172.26,53.49 172.25,53.4 172.25,53.2 172.48,52.63 173.05,52.4 173.75,52.4 174.06,52.46 174.33,52.65 174.44,52.67 174.5,52.58 174.5,51.4 174.47,51.33 174.4,51.3
N18162939 on BOTTOM: 159.59,47.2 159.53,47.22 159.5,47.27 159.48,47.32 159.42,47.44 159.41,47.52 159.41,47.54 159.41,47.66 159.41,47.68 159.43,47.78 159.48,47.87 159.71,48.07 159.76,48.12 160.51,48.87 160.54,48.89 160.58,48.9 162.7,48.9 166.17,52.37 166.2,52.39 166.24,52.4 173.8,52.4 173.82,52.4 173.91,52.35 174.1,52.2 174.19,51.98 174.19,51.96 174.19,51.84 174.19,51.82 174.08,51.57 173.61,51.29 173.45,51.06 173.42,51.02 173.36,51 166.5,51 162.73,47.23 162.7,47.21 162.66,47.2
N18174803 on TOP (solid shape): 201.84,134 201.99,133.65 201.86,133.31 201.54,133.15 201.43,132.91 201.43,132.9 201.37,132.2 200.66,132.27 199.89,133.21 199.81,133.72 200.23,134.03 201.49,134.15
N18174803 on BOTTOM (solid shape): 200.3,133.07 200.56,133.31 200.8,133.06 200.79,132.87 201.42,132.24 201.59,132.25 201.86,132.02 201.62,131.75 200.5,131.69 200.31,131.76 200.24,131.95
N18174803 on TOP: 201.05,138 200.7,138.15 200.55,138.5 200.55,140.4 200.7,140.75 201.05,140.9 201.49,140.9 201.68,140.86 201.85,140.75 202.85,139.75 202.96,139.58 203,139.39 203,139.01 202.96,138.82 202.85,138.65 202.35,138.15 202.18,138.04 201.99,138
N18174803 on BOTTOM: 200.6,137.9 200.53,137.93 200.5,138 200.5,140.76 200.51,140.8 200.53,140.83 203.17,143.47 203.2,143.49 203.24,143.5 205.76,143.5 205.99,143.55 206.18,143.68 206.96,144.45 207.29,144.94 207.4,145.51 207.41,145.7 207.4,145.86 207.41,145.9 207.43,145.93 207.67,146.17 207.7,146.19 207.74,146.2 208.5,146.2 208.58,146.17 208.6,146.09 208.6,145.95 208.6,145.9 208.6,144.24 208.6,144.2 208.58,144.17 206.83,142.42 206.8,142.4 206.76,142.4 203.8,142.4 202.9,141.5 202.9,138.94 202.89,138.9 202.87,138.87 201.93,137.93 201.9,137.91 201.86,137.9
N18174813 on BOTTOM (solid shape): 179.43,134.08 179.92,134.08 180.18,133.65 180.11,133.4 179.93,133.22 179.89,133.2 179.89,132.8 179.93,132.78 180.11,132.1 179.43,131.92 178.3,132.57 178.05,133 178.3,133.43
N18174813 on BOTTOM: 179.9,138.5 179.83,138.53 179.8,138.6 179.8,140.96 179.81,141 179.83,141.03 182.07,143.27 182.1,143.29 182.14,143.3 184.86,143.3 185.09,143.35 185.28,143.48 186.26,144.45 186.56,144.88 186.69,145.37 186.7,145.4 186.7,146.11 186.82,146.39 187.09,146.5 187.28,146.46 187.45,146.35 187.87,145.93 187.89,145.9 187.9,145.86 187.9,144.46 187.89,144.42 187.87,144.39 185.91,142.43 185.69,142.29 185.53,142.14 185.49,142.11 185.45,142.1 183.7,142.1 181.9,140.3 181.9,138.74 181.89,138.7 181.87,138.67 181.73,138.53 181.7,138.51 181.66,138.5
N18175726 on TOP: 197.23,143.77 197.21,143.8 197.2,143.84 197.2,144.76 197.21,144.8 197.23,144.83 197.35,144.95 197.37,144.97 197.52,145.08 197.63,145.23 197.67,145.27 197.7,145.29 197.74,145.3 199.42,145.3 199.45,145.3 199.48,145.28 200,145.1 200.53,145.22 200.63,145.22 200.68,145.14 200.73,144.91 200.87,144.72 200.91,144.67 200.93,144.56 200.84,144.5 200.75,144.5 200.41,144.42 200.13,144.2 200.05,144.17 199.97,144.2 199.69,144.42 199.35,144.5 198.65,144.5 198.08,144.27 197.85,143.7 197.85,143.5 197.85,143.45 197.86,143.4 197.8,143.29 197.69,143.31
N18188625 on TOP, BOTTOM: 12,104 12.15,104.35 12.5,104.5 13.25,104.5 14.75,106 13.25,107.5 12.5,107.5 12.15,107.65 12,108 12,109.5 12.15,109.85 12.5,110 21.5,110 21.85,109.85 22,109.5 22,87 21.85,86.65 21.5,86.5 12.5,86.5 12.15,86.65 12,87 ; 2 cut-outs
N18188625 on CONDUCTIVE2, CONDUCTIVE3: 12,104.1 12.15,104.45 12.5,104.6 13.25,104.6 14.65,106 13.25,107.4 12.5,107.4 12.15,107.55 12,107.9 12,109.5 12.15,109.85 12.5,110 21.5,110 21.85,109.85 22,109.5 22,87 21.85,86.65 21.5,86.5 12.5,86.5 12.15,86.65 12,87 ; 2 cut-outs
N18188823 on BOTTOM: 47,93.79 47.04,93.98 47.15,94.15 56.85,103.85 56.96,104.02 57,104.21 57,127.79 57.04,127.98 57.15,128.15 57.85,128.85 58.02,128.96 58.21,129 74.49,129 74.68,128.96 74.85,128.85 75.55,128.15 75.66,127.98 75.7,127.79 75.7,105.91 75.66,105.72 75.55,105.55 62.65,92.65 62.48,92.54 62.29,92.5 56.85,92.5 56.83,92.5 53.45,91.55 52.5,88.17 52.5,88.15 52.5,87 52.35,86.65 52,86.5 47.5,86.5 47.15,86.65 47,87 ; 4 cut-outs
N18188823 on CONDUCTIVE3: 47,93.79 47.04,93.98 47.15,94.15 56.85,103.85 56.96,104.02 57,104.21 57,127.79 57.04,127.98 57.15,128.15 57.85,128.85 58.02,128.96 58.21,129 74.49,129 74.68,128.96 74.85,128.85 75.55,128.15 75.66,127.98 75.7,127.79 75.66,105.72 75.56,105.56 62.65,92.65 62.48,92.54 62.29,92.5 56.85,92.5 56.83,92.5 53.45,91.55 52.5,88.17 52.5,88.15 52.5,87 52.35,86.65 52,86.5 47.5,86.5 47.15,86.65 47,87 ; 4 cut-outs
N18316863 on TOP: 95.53,57.99 95.5,58.03 95.51,58.18 95.64,58.25 96.04,58.25 96.07,58.25 96.18,58.14 96.14,57.99 95.94,57.79 95.84,57.75 95.73,57.79
N18316907 on TOP: 92.3,55.21 92.26,55.22 92.16,55.32 92.19,55.47 92.39,55.67 92.5,55.71 92.61,55.67 92.81,55.47 92.83,55.43 92.83,55.28 92.7,55.21
N18485742 on BOTTOM: 95.3,11.4 94.59,11.69 94.3,12.4 94.3,19.6 94.59,20.31 95.3,20.6 99.7,20.6 100.41,20.31 100.7,19.6 100.7,14.1 102,12.81 103.3,14.1 103.3,16.35 104.15,17.2 105,16.35 105,12.4 104.71,11.69 104,11.4
N18485742 on CONDUCTIVE3: 94.3,19.8 94.53,20.37 95.1,20.6 103,20.6 103.57,20.37 103.8,19.8 103.8,15.6 103.57,15.03 103,14.8 102.31,14.8 102.28,14.81 102,14.86 101.72,14.81 101.69,14.8 95.1,14.8 94.53,15.03 94.3,15.6 ; 2 cut-outs

Small or netless copper shapes (teardrops, artwork), in the pictures only: 995 on TOP, 101 on BOTTOM, 12 on CONDUCTIVE2, 6 on CONDUCTIVE3

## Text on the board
PAGE_OUTLINE: F1 | AC(L) | AC(N) | 2 | 1 | L1 | PS1 | LED1 | C10 | R11 | C121 | L2 | RLY2 | TP11 | -Vo | +Vo | 4 | 3 | C11 | IC13 | C71 | TP44 | CN7 | C75 | Q2 | C72 | R84 | CT1 | L4 | C3 | 14 | R17 | TP45 | R12 | R82 | R2 | R79 | D2 | R78 | TP46 | R1 | C4 | R5 | R91 | L8 | R97 | R4 | R92 | R94 | R93 | C87 | TP57 | TP54 | 8 | C50 | R13 | C82 | PC2 | C81 | PS7 | C35 | TP12 | C37 | 7 | C36 | TP43 | R60 | TP74 | R57 | R58 | R59 | L3 | R46 | R43 | TP66 | C41 | A | Q6 | C | C42 | R49 | 16 | C40 | C107 | TP67 | R134 | TP56 | C108 | C43 | R135 | R133 | D18 | C58 | C56 | S | C32 | R132 | G | R136 | D10 | D13 | C39 | C59 | R67 | R130 | R37 | Q5 | C31 | R131 | C33 | C60 | R64 | R42 | C34 | LED5 | LED4 | IC19 | IC10 | C57 | TP69 | C25 | C24 | D20 | C67 | R137 | R138 | C23 | C65 | R30 | C26 | TP68 | Q4 | C68 | R74 | C15 | C20 | R18 | C69 | TP72 | R77 | C14 | R139 | D8 | D4 | C16 | IC12 | C66 | TP70 | R26 | Q3 | R140 | C22 | IC2 | C21 | C115 | C114 | C48 | CN8 | C113 | C112 | TP52 | C54 | TP71 | R127 | TP51 | IC14 | L10 | R122 | TP58 | C99 | L7 | R123 | C100 | R116 | R125 | IC17 | R115 | R117 | D25 | R121 | TP61 | R119 | C93 | C88 | R96 | L9 | R113 | R110 | R107 | C94 | C95 | R112 | TP59 | R103 | L6 | R104 | R106 | TP60 | C104 | C105 | R141 | TP65 | C49 | C55 | C109 | 60 | 59 | TB3 | TB2 | TB1 | ZNR1 | C122 | R3 | C2 | TP8 | TP10 | C123 | C8 | C9 | C120 | ZD1 | TP7 | TP47 | C74 | R83 | C77 | TP53 | C76 | C70 | D22 | R80 | R81 | C73 | TP49 | TP50 | R90 | R88 | R89 | R85 | PS9 | IC15 | LED3 | R100 | L5 | C85 | TP9 | C86 | R87 | C7 | TP2 | TP48 | R86 | C84 | D23 | C83 | C80 | TP55 | PS10 | R15 | R14 | C51 | IC6 | C52 | PS5 | R45 | R44 | IC7 | IC9 | R48 | R47 | TP33 | C38 | D12 | D14 | C53 | D7 | C6 | R50 | R66 | D15 | R51 | R65 | IC5 | D17 | R39 | R38 | R62 | D27 | R40 | D28 | R63 | IC3 | R29 | D16 | R28 | R41 | D11 | D6 | Q7 | 20 | R76 | C106 | D19 | R75 | R31 | R20 | R32 | R72 | R19 | D9 | D29 | R73 | D21 | IC1 | Q8 | D26 | R21 | C111 | C110 | R23 | D5 | R27 | C19 | C17 | R22 | C18 | R25 | R24 | R56 | R61 | C79 | PS3 | IC18 | R128 | C78 | TP62 | C97 | C89 | R124 | R118 | R126 | R99 | C96 | R98 | C98 | C92 | R111 | R95 | R102 | R120 | R114 | R109 | R108 | R101 | C91 | R105 | IC16 | D24 | C90 | C101 | C102 | C103 | IC20 | PS11 | R129 | TP64 | TP63 | TB4 | TB5 | 24V | /RDY | FLT | 5V | GND | FG | AC L | AC N | HSP0248-B00-0001A
User.7: CN4 | CN5 | CN6 | CN2 | CN1 | TP28 | TP27 | TP31 | TP36 | CN3 | TP26 | TP37 | TP22 | TP42 | TP19 | TP18 | TP17
